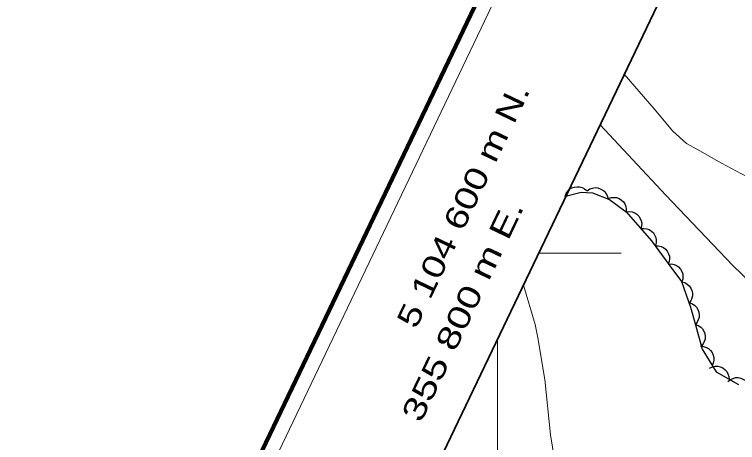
# Model space of a CAD drawing. Extents: x 355726 to 357533, y 5103782 to 5105258.
# Drawn here: x 355767.6 to 355816.1, y 5104587.31 to 5104616.01 of the extents above; entities that cross this region are included whole.
import ezdxf
from ezdxf.enums import TextEntityAlignment as Align

# ---------------------------------------------------------------- set-up
doc = ezdxf.new("R2010")
doc.units = 0
doc.header["$LTSCALE"] = 0.6
doc.linetypes.add('DOT_DASHED', pattern=[7.7, 5, -1.2, 0.3, -1.2])
doc.linetypes.add('LONG_DASHED', pattern=[7.5, 6, -1.5])
for name, color, linetype, lineweight in [('19', 7, 'Continuous', 13), ('2', 7, 'LONG_DASHED', 13), ('44', 7, 'Continuous', 25), ('60', 7, 'Continuous', 13), ('61', 7, 'Continuous', 13)]:
    doc.layers.add(name, color=color, linetype=linetype, lineweight=lineweight)

msp = doc.modelspace()

# ---------------------------------------------------------------- linework, layer by layer
at = {"layer": '19'}
for points in [[(355808.49, 5104612.02), (355810.51, 5104609.68), (355811.75, 5104608.19), (355812.68, 5104607.37), (355813.58, 5104606.86), (355815.02, 5104606.05), (355817.37, 5104604.79), (355818.36, 5104604.43), (355818.94, 5104604.4), (355820.45, 5104604.24), (355820.83, 5104604.22), (355821.43, 5104604.38), (355822.1, 5104604.69), (355822.66, 5104604.96), (355823.15, 5104605.48), (355823.73, 5104606.14), (355824.31, 5104606.8), (355829.27, 5104611.61), (355832.71, 5104614.68), (355837, 5104609.98), (355834.08, 5104606.98), (355832.2, 5104605.28)], [(355806.87, 5104608.64), (355811.29, 5104603.9), (355815.78, 5104599.19), (355820.21, 5104594.91), (355820.84, 5104594.45), (355821.65, 5104595.18)]]:
    msp.add_lwpolyline(points, dxfattribs=at)
at = {"layer": '2', "linetype": 'Continuous'}
msp.add_lwpolyline([(355816.68, 5104583.23), (355813.63, 5104580.18), (355812.97, 5104579.74), (355812.31, 5104579.71), (355811.98, 5104579.8), (355811, 5104580.26), (355810.6, 5104580.33), (355809.29, 5104580.17), (355808.87, 5104580.16), (355808.51, 5104580.24), (355805.93, 5104581.62), (355805.55, 5104581.88), (355805.18, 5104582.24), (355804.86, 5104582.7), (355804.57, 5104583.25), (355804.33, 5104583.87), (355803.95, 5104585.34), (355803.55, 5104587.82), (355803.17, 5104591.53), (355802.7, 5104594.32), (355802.53, 5104595.23), (355801.74, 5104597.87)], dxfattribs=at)
at = {"layer": '44'}
for points in [[(355804.53, 5104603.8), (355804.6, 5104604), (355804.72, 5104604.17), (355804.83, 5104604.29), (355804.98, 5104604.38), (355805.15, 5104604.44), (355805.34, 5104604.46), (355805.51, 5104604.46), (355805.67, 5104604.41), (355805.84, 5104604.32), (355805.98, 5104604.2)], [(355806.02, 5104604.19), (355806.19, 5104604.31), (355806.38, 5104604.37), (355806.54, 5104604.4), (355806.72, 5104604.38), (355806.89, 5104604.33), (355807.06, 5104604.23), (355807.19, 5104604.14), (355807.29, 5104603.99), (355807.37, 5104603.83), (355807.41, 5104603.65)], [(355807.43, 5104603.68), (355807.63, 5104603.75), (355807.83, 5104603.75), (355807.99, 5104603.74), (355808.16, 5104603.67), (355808.31, 5104603.57), (355808.45, 5104603.44), (355808.55, 5104603.31), (355808.6, 5104603.14), (355808.64, 5104602.96), (355808.63, 5104602.78)], [(355808.63, 5104602.78), (355808.84, 5104602.81), (355809.04, 5104602.77), (355809.2, 5104602.72), (355809.34, 5104602.62), (355809.47, 5104602.49), (355809.57, 5104602.33), (355809.64, 5104602.18), (355809.67, 5104602.01), (355809.66, 5104601.82), (355809.62, 5104601.65)], [(355809.62, 5104601.65), (355809.82, 5104601.67), (355810.02, 5104601.64), (355810.18, 5104601.59), (355810.33, 5104601.49), (355810.46, 5104601.36), (355810.56, 5104601.2), (355810.63, 5104601.05), (355810.65, 5104600.88), (355810.65, 5104600.69), (355810.6, 5104600.52)], [(355810.57, 5104600.49), (355810.78, 5104600.5), (355810.98, 5104600.45), (355811.13, 5104600.39), (355811.27, 5104600.27), (355811.39, 5104600.13), (355811.47, 5104599.96), (355811.53, 5104599.81), (355811.54, 5104599.63), (355811.52, 5104599.45), (355811.45, 5104599.28)], [(355811.45, 5104599.28), (355811.66, 5104599.29), (355811.86, 5104599.24), (355812.01, 5104599.18), (355812.15, 5104599.08), (355812.28, 5104598.94), (355812.37, 5104598.77), (355812.43, 5104598.62), (355812.44, 5104598.44), (355812.42, 5104598.26), (355812.37, 5104598.09)], [(355812.36, 5104598.09), (355812.56, 5104598.03), (355812.73, 5104597.92), (355812.86, 5104597.82), (355812.96, 5104597.67), (355813.03, 5104597.5), (355813.07, 5104597.32), (355813.08, 5104597.15), (355813.03, 5104596.98), (355812.96, 5104596.81), (355812.85, 5104596.67)], [(355812.87, 5104596.67), (355813.07, 5104596.61), (355813.23, 5104596.49), (355813.35, 5104596.38), (355813.44, 5104596.23), (355813.51, 5104596.05), (355813.53, 5104595.86), (355813.53, 5104595.7), (355813.47, 5104595.53), (355813.39, 5104595.37), (355813.27, 5104595.23)], [(355813.27, 5104595.23), (355813.47, 5104595.16), (355813.64, 5104595.04), (355813.76, 5104594.93), (355813.85, 5104594.78), (355813.91, 5104594.61), (355813.93, 5104594.42), (355813.93, 5104594.25), (355813.87, 5104594.08), (355813.79, 5104593.92), (355813.67, 5104593.78)], [(355813.61, 5104593.76), (355813.82, 5104593.75), (355814.01, 5104593.68), (355814.16, 5104593.61), (355814.29, 5104593.48), (355814.4, 5104593.34), (355814.47, 5104593.16), (355814.51, 5104593), (355814.51, 5104592.83), (355814.47, 5104592.64), (355814.4, 5104592.48)], [(355814.22, 5104592.3), (355814.41, 5104592.39), (355814.61, 5104592.42), (355814.77, 5104592.43), (355814.94, 5104592.39), (355815.11, 5104592.31), (355815.26, 5104592.19), (355815.38, 5104592.07), (355815.46, 5104591.92), (355815.51, 5104591.74), (355815.53, 5104591.56)], [(355815.46, 5104591.4), (355815.62, 5104591.53), (355815.81, 5104591.61), (355815.96, 5104591.66), (355816.14, 5104591.66), (355816.32, 5104591.62), (355816.5, 5104591.54), (355816.64, 5104591.46), (355816.75, 5104591.32), (355816.85, 5104591.17), (355816.91, 5104591)]]:
    msp.add_lwpolyline(points, dxfattribs=at)
at = {"layer": '44', "linetype": 'DOT_DASHED'}
msp.add_lwpolyline([(355804.54, 5104603.78), (355804.66, 5104603.84), (355805.6, 5104604.1), (355806.38, 5104604.05), (355807.52, 5104603.61), (355808.64, 5104602.77), (355810.32, 5104600.84), (355811.55, 5104599.15), (355812.35, 5104598.11), (355812.95, 5104596.38), (355813.28, 5104595.21), (355813.73, 5104593.57), (355814.66, 5104592.05), (355816.17, 5104591.2)], dxfattribs=at)
at = {"layer": '60', "lineweight": 158}
msp.add_lwpolyline([(355725.74, 5104464.62), (357152.72, 5103781.6), (357532.66, 5104575.38), (356105.68, 5105258.4)], close=True, dxfattribs=at)
at = {"layer": '60'}
msp.add_lwpolyline([(355727.1, 5104465.08), (357152.24, 5103782.93), (357531.32, 5104574.91), (356106.18, 5105257.06)], close=True, dxfattribs=at)
at = {"layer": '60', "lineweight": 35}
msp.add_lwpolyline([(355740.43, 5104469.78), (356913.03, 5103908.53), (357283.46, 5104682.46), (356110.86, 5105243.71)], close=True, dxfattribs=at)
at = {"layer": '61'}
for p, q in [((355808.3, 5104600), (355802.76, 5104600)), ((355800, 5104582.65), (355800, 5104594.24))]:
    msp.add_line(p, q, dxfattribs=at)

# ---------------------------------------------------------------- texts
for s, width, p in [(' 5 104 600 m N.', 1.3, (355798.219, 5104602.571)), (' 355 800 m E.', 1.35, (355798.17, 5104595.496))]:
    msp.add_text(s, height=1.5, rotation=64.42, dxfattribs=dict(at, width=width)).set_placement(p, align=Align.CENTER)

doc.saveas('drawing.dxf')
